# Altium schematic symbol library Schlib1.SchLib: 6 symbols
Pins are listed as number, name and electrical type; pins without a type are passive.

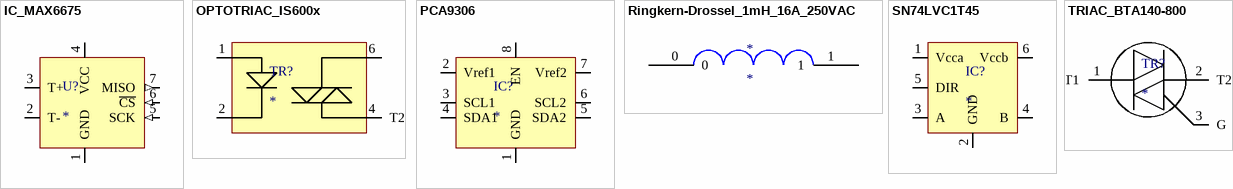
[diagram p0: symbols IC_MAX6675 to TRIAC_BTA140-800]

## IC_MAX6675
designator U?
footprint IC_SOIC150_8 (SOIC, 1.27mm, 150mil body)
pins: 1 GND, 2 T-, 3 T+, 4 VCC (power), 5 SCK (in), 6 ~{CS} (in), 7 MISO (out)

## OPTOTRIAC_IS600x
designator TR?
footprint DIP-6 (DIP, 6-Pin, Row Spacing 7.62 mm, Pitch 2.54 mm)
pins: 1 LED A, 2 LED K, 4 T2, 6 T1

## PCA9306
designator IC?
footprint SM8
pins: 1 GND, 2 Vref1 (power), 3 SCL1, 4 SDA1, 5 SDA2, 6 SCL2, 7 Vref2 (power), 8 EN

## Ringkern-Drossel_1mH_16A_250VAC
designator *
footprint PCBComponent_1 - duplicate
pins: 0, 1

## SN74LVC1T45
designator IC?
footprint IC_SOT23-6
pins: 1 Vcca (power), 2 GND, 3 A, 4 B, 5 DIR, 6 Vccb (power)

## TRIAC_BTA140-800
designator TR?
footprint TO-220L
footprint TO-220
pins: 1 T1, 2 T2, 3 G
